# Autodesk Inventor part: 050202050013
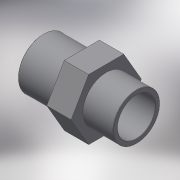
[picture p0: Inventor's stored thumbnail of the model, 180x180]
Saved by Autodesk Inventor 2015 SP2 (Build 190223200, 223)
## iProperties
Created: 2017-10
Part Number: 050202050013
Material: Generic
Description: PLASSON REDUCER THR-CEM PVC 50(40)1.1/4"F
Document SubType Name: Modeling
Designer: KIM
Density: 1 g/cm^3
Appearance: Default
Author: KIM
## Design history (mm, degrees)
derived "050202.ipt"
feature "Solid1::050202.ipt"
tag "TaggingFeature1"
body "Solid1"
other parameters: "d0" = 68, "d2" = 65, "d3" = 38.952, "d4" = 36, "d6" = 22, "d8" = 46, "d13" = 0, "d14" = 0.4, "d16" = 16, "d17" = 31, "d18" = 26.4, "G_" = 38.952, "C_" = 65, "B_" = 16, "L_" = 31, "lt_" = 22, "H_" = 68
